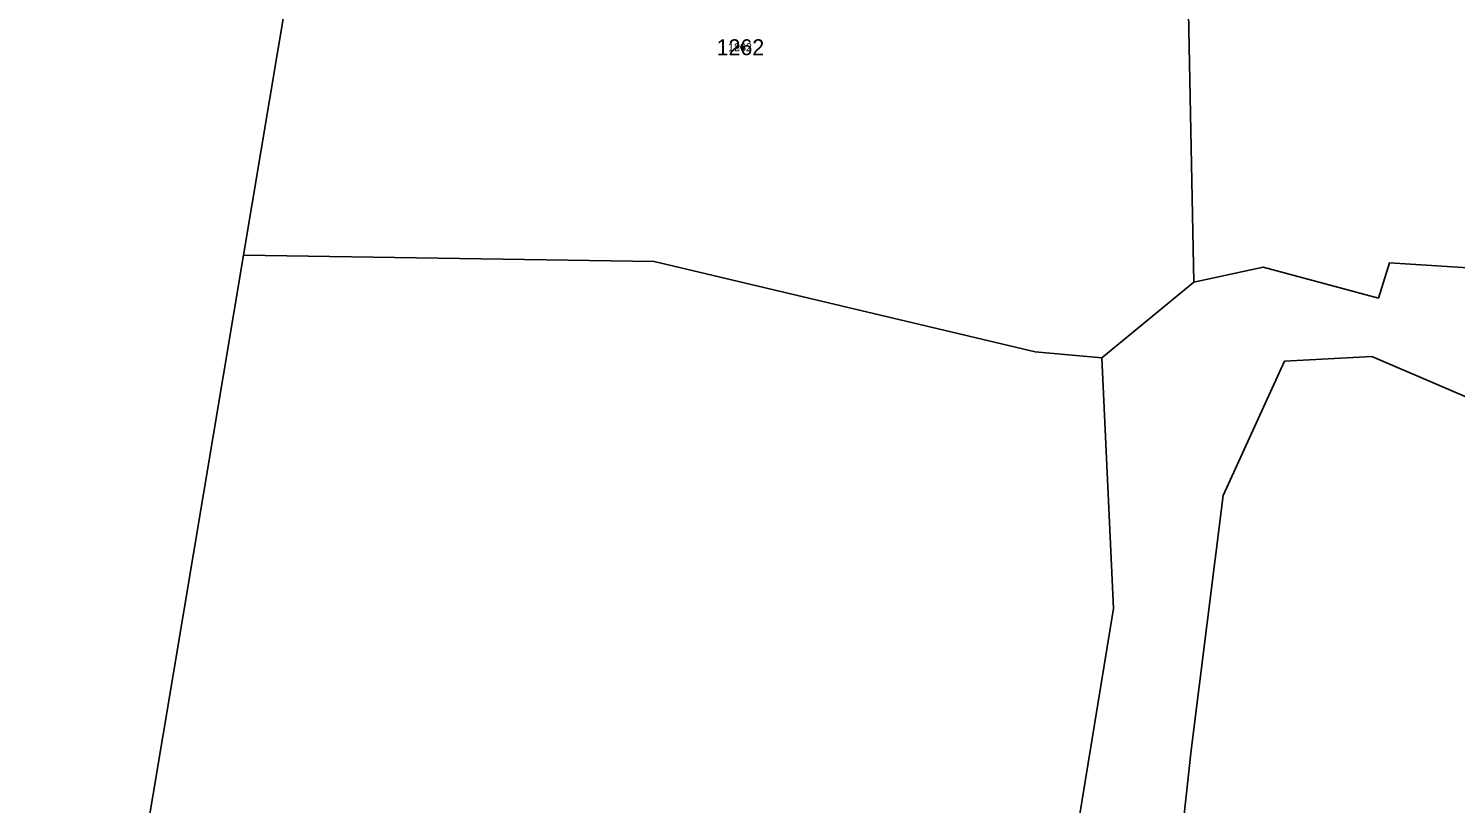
# Model space of a CAD drawing. Extents: x -744652 to -739090, y -980828 to -975855.
# Drawn here: x -741196 to -741044.4, y -979147.7 to -979065.4 of the extents above; entities that cross this region are included whole.
import ezdxf

# ---------------------------------------------------------------- set-up
doc = ezdxf.new("R2010")
doc.units = 0
for name, color, linetype in [('KAT_02_hranice parcel', 7, 'Continuous'), ('KAT_03_1000_čísla parcelní', 7, 'Continuous'), ('KAT_03_100_čísla parcelní', 7, 'Continuous'), ('KAT_03_250_čísla parcelní', 7, 'Continuous'), ('KAT_03_500_čísla parcelní', 7, 'Continuous')]:
    doc.layers.add(name, color=color, linetype=linetype)

msp = doc.modelspace()

# ---------------------------------------------------------------- linework, layer by layer
at = {"layer": 'KAT_02_hranice parcel'}
for p, q in [((-741160.19, -979012.17), (-741173.15, -979089.48)), ((-741072.23, -979092.36), (-741082, -979100.38))]:
    msp.add_line(p, q, dxfattribs=at)
for points in [[(-741118.87, -979024.66), (-741115.02, -979020.6), (-741079.59, -979033.41), (-741073.31, -979036.93), (-741072.23, -979092.36)], [(-741072.23, -979092.36), (-741064.87, -979090.77), (-741052.62, -979094.05), (-741051.46, -979090.32), (-741034.16, -979091.39), (-741020.83, -979087.35), (-740998.61, -979103.51), (-740995.38, -979099.09)], [(-741173.15, -979089.48), (-741188.06, -979178.38), (-741195.98, -979215.67)], [(-741173.15, -979089.48), (-741129.55, -979090.17), (-741089.06, -979099.76), (-741082, -979100.38)], [(-741082, -979100.38), (-741080.77, -979126.99), (-741087.44, -979167.82), (-741090.41, -979190), (-741095.02, -979203.52), (-741107.74, -979255.08), (-741107.56, -979289.63)], [(-741107.56, -979289.63), (-741096.37, -979290.03), (-741092.93, -979259.39), (-741086.96, -979230.03), (-741078.03, -979188.76), (-741075.53, -979169.67), (-741072.5, -979142.03), (-741069.12, -979115.02), (-741062.59, -979100.73), (-741053.31, -979100.26), (-741041.19, -979105.44), (-741016.38, -979118.51), (-740999.96, -979123.65), (-740984.63, -979125.47), (-740977.31, -979119.48)]]:
    msp.add_lwpolyline(points, dxfattribs=at)

# ---------------------------------------------------------------- texts
at = {"layer": 'KAT_03_1000_čísla parcelní'}
msp.add_text('1262', height=1.7, dxfattribs=at).set_placement((-741122.91, -979068.28))
at = {"layer": 'KAT_03_100_čísla parcelní'}
msp.add_text('1262', height=0.17, dxfattribs=at).set_placement((-741120.71, -979067.51))
at = {"layer": 'KAT_03_250_čísla parcelní'}
msp.add_text('1262', height=0.425, dxfattribs=at).set_placement((-741121.07, -979067.64))
at = {"layer": 'KAT_03_500_čísla parcelní'}
msp.add_text('1262', height=0.85, dxfattribs=at).set_placement((-741121.69, -979067.85))

doc.saveas('drawing.dxf')
